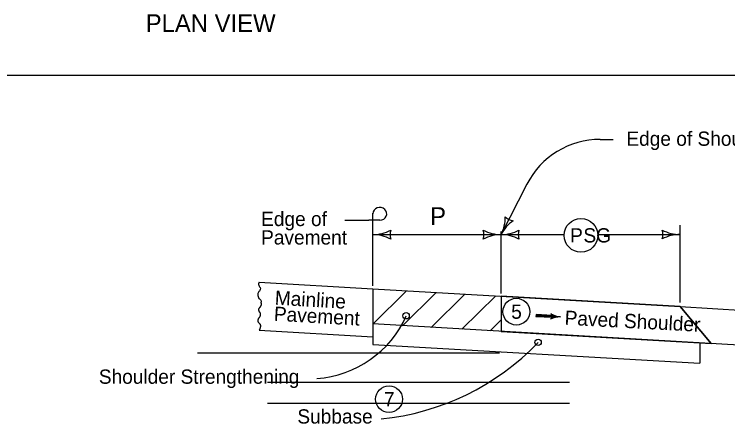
# Model space of a CAD drawing. Extents: x 10133 to 81668, y 7924 to 12229.
# Drawn here: x 11002 to 11801, y 11270 to 11730 of the extents above; entities that cross this region are included whole.
import ezdxf

# ---------------------------------------------------------------- set-up
doc = ezdxf.new("R2010")
doc.units = 0
for name, color, linetype in [('Cell', 7, 'Continuous'), ('dsnTextFinalPlan', 7, 'Continuous'), ('Level 12', 7, 'Continuous'), ('Level 21', 7, 'Continuous'), ('Level 4', 7, 'Continuous'), ('Level 6', 7, 'Continuous'), ('SheetText', 7, 'Continuous')]:
    doc.layers.add(name, color=color, linetype=linetype)

msp = doc.modelspace()

# ---------------------------------------------------------------- linework, layer by layer
at = {"layer": 'Cell'}
for p, q in [((11547.43, 11413.66), (11547.4, 11373.85)), ((11747.93, 11402.08), (11547.43, 11413.66)), ((11782.96, 11360.55), (11747.93, 11402.08)), ((11547.4, 11373.85), (11782.96, 11360.55))]:
    msp.add_line(p, q, dxfattribs=at)
at = {"layer": 'dsnTextFinalPlan'}
for p, q in [((11276.17, 11429.43), (11403.63, 11422.02)), ((11403.63, 11422.02), (11403.63, 11368.01)), ((11403.63, 11422.02), (11747.92, 11402)), ((11547.4, 11413.65), (11547.4, 11373.85)), ((11747.46, 11402.19), (11747.46, 11402.19)), ((11747.92, 11402), (11782.96, 11360.55)), ((11747.93, 11402.08), (11882.68, 11393.7)), ((11979.73, 11349.21), (11403.63, 11382.43)), ((11276.2, 11375.42), (11403.63, 11368.01)), ((11770.16, 11375.7), (11770.16, 11375.7)), ((11403.63, 11368.01), (11403.63, 11359.59)), ((11403.63, 11359.59), (11770.16, 11338.45)), ((11770.16, 11361.28), (11770.16, 11338.45)), ((11206.91, 11350.08), (11545.41, 11350.08)), ((11285.58, 11317.1), (11624.08, 11317.1)), ((11285.58, 11293.43), (11624.08, 11293.43))]:
    msp.add_line(p, q, dxfattribs=at)
for points in [[(11276.17, 11429.43), (11275.66, 11425.83), (11276.7, 11424.32), (11277.57, 11422.03), (11276.96, 11419.97), (11275.06, 11417.59), (11274.54, 11415.69), (11275.06, 11413.39), (11275.92, 11411.02), (11276.96, 11410.31), (11278.35, 11407.77), (11278.34, 11406.93)], [(11276.38, 11389.82), (11276.59, 11390.07), (11276.79, 11390.33), (11277.14, 11390.89), (11277.42, 11391.48), (11277.54, 11391.78), (11277.63, 11392.1), (11277.77, 11392.72), (11277.82, 11393.34), (11277.77, 11393.93), (11277.71, 11394.2), (11277.67, 11394.34), (11277.63, 11394.47), (11277.42, 11394.85), (11277.14, 11395.21), (11276.84, 11395.58), (11276.59, 11395.97), (11276.45, 11396.26), (11276.31, 11396.54), (11276.05, 11397.11), (11275.85, 11397.68), (11275.77, 11397.97), (11275.72, 11398.27), (11275.71, 11398.4), (11275.71, 11398.53), (11275.86, 11399.3), (11276.07, 11399.82), (11276.33, 11400.33), (11276.77, 11400.97), (11277.29, 11401.51), (11277.8, 11402.06), (11278.03, 11402.37), (11278.23, 11402.71), (11278.44, 11403.18), (11278.6, 11403.65), (11278.7, 11404.13), (11278.73, 11404.37), (11278.75, 11404.49), (11278.75, 11404.61), (11278.71, 11405.12), (11278.56, 11405.63), (11278.51, 11405.76), (11278.45, 11405.88), (11278.4, 11406.01), (11278.38, 11406.14), (11278.34, 11406.93)], [(11276.38, 11389.82), (11276.16, 11389.58), (11275.92, 11389.35), (11275.68, 11389.11), (11275.5, 11388.84), (11275.36, 11388.56), (11275.22, 11388.27), (11274.96, 11387.7), (11274.85, 11387.42), (11274.75, 11387.13), (11274.68, 11386.84), (11274.65, 11386.69), (11274.63, 11386.54), (11274.64, 11386.03), (11274.77, 11385.51), (11274.98, 11384.99), (11275.24, 11384.48), (11275.68, 11383.85), (11276.2, 11383.3), (11276.71, 11382.75), (11276.94, 11382.45), (11277.14, 11382.11), (11277.55, 11381.16), (11277.65, 11380.69), (11277.66, 11380.21), (11277.63, 11379.92), (11277.58, 11379.63), (11277.53, 11379.34), (11277.46, 11379.06), (11277.14, 11377.91), (11276.96, 11377.3), (11276.77, 11376.7), (11276.55, 11376.11), (11276.42, 11375.82), (11276.28, 11375.53), (11276.2, 11375.42)]]:
    msp.add_spline(points, degree=3, dxfattribs=at)
at = {"layer": 'Level 12'}
for centre in [(11564.45, 11396.26), (11421.73, 11298.06)]:
    msp.add_circle(centre, 15, dxfattribs=at)
at = {"layer": 'Level 21'}
msp.add_circle((11564.45, 11396.26), 15, dxfattribs=at)
at = {"layer": 'Level 4'}
msp.add_line((12302.71, 11661.22), (10147.13, 11661.22), dxfattribs=at)
for centre in [(11440.93, 11391.61), (11440.93, 11391.61), (11588.87, 11361.76), (11588.87, 11361.76)]:
    msp.add_circle(centre, 3.54, dxfattribs=at)
at = {"layer": 'SheetText'}
for p, q in [((11658.59, 11589.68), (11672.9, 11589.68)), ((11576.29, 11539.31), (11547.39, 11482.75)), ((11403.63, 11486.07), (11403.63, 11506.93)), ((11372.26, 11498.92), (11398.94, 11498.92)), ((11411.44, 11498.92), (11398.94, 11498.92)), ((11747.93, 11406.64), (11747.93, 11493.3)), ((11403.63, 11425.16), (11403.63, 11486.07)), ((11547.39, 11416.52), (11547.39, 11486.07)), ((11403.63, 11482.75), (11617.95, 11482.75)), ((11655.77, 11482.91), (11747.93, 11482.91)), ((11403.63, 11382.42), (11441.42, 11419.82)), ((11436.67, 11380.52), (11474.46, 11417.92)), ((11468.91, 11378.66), (11506.7, 11416.06)), ((11503.52, 11376.66), (11541.31, 11414.06)), ((11604.66, 11390.91), (11586.45, 11391.96)), ((11604.55, 11389.97), (11604.55, 11389.97)), ((11604.67, 11391.92), (11604.67, 11391.92)), ((11535.14, 11374.84), (11547.4, 11386.97))]:
    msp.add_line(p, q, dxfattribs=at)
for points in [[(11604.68, 11391.85), (11586.52, 11392.9), (11586.39, 11391.02), (11604.55, 11389.97), (11604.61, 11391.59), (11586.74, 11392.68), (11586.68, 11391.18), (11604.17, 11390.23), (11604.29, 11391.35), (11586.97, 11392.41), (11586.95, 11391.41), (11603.96, 11390.43), (11604.05, 11391.14), (11587.16, 11392.19), (11587.14, 11391.63), (11603.75, 11390.7)], [(11604.28, 11393.11), (11604.97, 11391.94), (11604.95, 11390.29), (11604.19, 11388.9), (11606.95, 11389.76), (11610.14, 11390.41), (11611.04, 11390.55), (11608.8, 11391.09), (11605.57, 11392.32), (11604.63, 11392.86), (11604.75, 11389.34), (11609.7, 11390.56), (11605.06, 11392.14), (11605.07, 11389.72), (11608.47, 11390.65), (11605.47, 11391.51), (11605.24, 11390.13), (11607.4, 11390.63), (11605.81, 11391.14), (11605.67, 11390.48), (11606.46, 11390.64)]]:
    msp.add_lwpolyline(points, dxfattribs=at)
msp.add_circle((11636.87, 11481.93), 18.93, dxfattribs=at)
for centre, radius, start, end in [((11658.59, 11497.25), 92.43, 90, 152.9341), ((11509.54, 11502.09), 42.5, 332.9341, 1.00659), ((11563.6, 11514.48), 16.42, 225.20075, 260.66745), ((11585.23, 11463.41), 42.5, 124.86161, 152.9341), ((11403.63, 11525.25), 42.5, 270, 298.07249), ((11439.27, 11482.75), 16.42, 162.26665, 197.73335), ((11511.75, 11482.75), 16.42, 342.26665, 17.73335), ((11547.39, 11525.25), 42.5, 241.92751, 270), ((11547.39, 11525.25), 42.5, 270, 298.07249), ((11583.02, 11482.75), 16.42, 162.26665, 197.73335), ((11712.29, 11482.91), 16.42, 342.26665, 17.73335), ((11747.93, 11525.41), 42.5, 241.92751, 270), ((11403.63, 11440.25), 42.5, 61.92751, 90), ((11547.39, 11440.25), 42.5, 90, 118.07249), ((11547.39, 11440.25), 42.5, 61.92751, 90), ((11747.93, 11440.41), 42.5, 90, 118.07249), ((11332.38, 11439.78), 118.88, 274.08506, 336.06992), ((11384.91, 11556.52), 282.03, 275.67842, 316.28441)]:
    msp.add_arc(centre, radius, start, end, dxfattribs=at)
for centre, major_axis, start_param, end_param in [((11411.44, 11506.05), (-7.81, 0), 1.570796, 6.283185), ((11600.89, 11391.13), (3.88, 0), 5.202895, 7.237436), ((11613.16, 11370.13), (22.17, 0), 1.537172, 2.061295), ((11615.95, 11410.55), (-22.17, 0), 0.954258, 1.478381)]:
    msp.add_ellipse(centre, major_axis=major_axis, ratio=0.913811, start_param=start_param, end_param=end_param, dxfattribs=at)

# ---------------------------------------------------------------- texts
at = {"layer": 'Level 12'}
for s, p in [('5', (11558.68, 11388.26)), ('7', (11416.03, 11290.06))]:
    msp.add_text(s, height=16, dxfattribs=at).set_placement(p)
at = {"layer": 'Level 6'}
msp.add_text('PLAN VIEW', height=20, dxfattribs=at).set_placement((11148.99, 11710.11))
msp.add_text('PLAN VIEW', height=20, dxfattribs=at).set_placement((11148.99, 11710.11))
at = {"layer": 'SheetText'}
for s, height, p in [('Edge of Shoulder Strengthening', 16, (11687.79, 11582.44)), ('Edge of ', 16, (11278.37, 11492.34)), ('P', 20, (11467.79, 11493.5)), ('Pavement', 16, (11278.37, 11471.63)), ('P', 16, (11624.74, 11473.93)), ('SG', 16, (11639.65, 11473.93)), ('Shoulder Strengthening', 16, (11096.48, 11315.32)), ('Subbase', 16, (11319, 11270.68))]:
    msp.add_text(s, height=height, dxfattribs=at).set_placement(p)
for s, rotation, p in [('Mainline', 356.73462, (11293.39, 11404.09)), ('Pavement', 356.73462, (11292.36, 11386.12)), ('Paved Shoulder ', 356.98301, (11618.27, 11381.64))]:
    msp.add_text(s, height=16, rotation=rotation, dxfattribs=at).set_placement(p)

doc.saveas('drawing.dxf')
